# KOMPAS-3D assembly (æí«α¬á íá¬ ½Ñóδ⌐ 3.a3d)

Referenced files in D:\АСКОН работа\Конкурс HOME\06_Сюваев_Сборная модель танка Т90\ДЕТАЛИ\КОРПУС\МЕТАЛЛ\КОРПУС ШТАМПОВКА\БАКИ\: бак левый 3.m3d
Referenced files in D:\АСКОН работа\Конкурс HOME\06_Сюваев_Сборная модель танка Т90\ДЕТАЛИ\ОБЩИЕ ДЕТАЛИ\: шарниры ящиков.m3d, замки ящиков.m3d
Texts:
  Сборка бак левый 3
